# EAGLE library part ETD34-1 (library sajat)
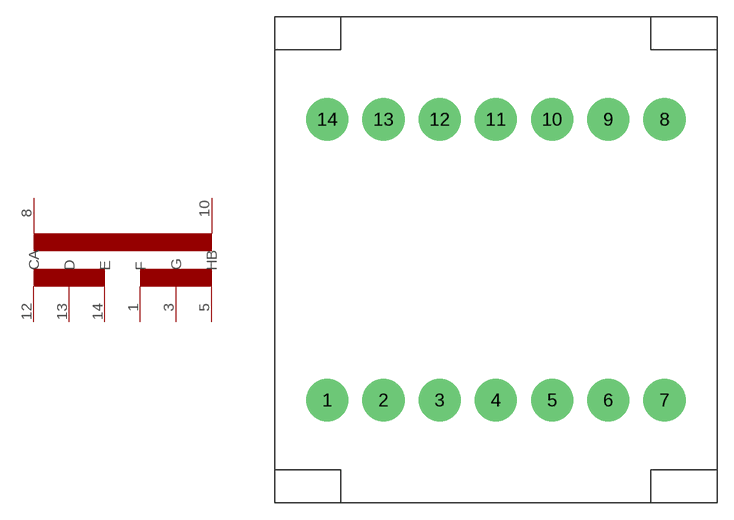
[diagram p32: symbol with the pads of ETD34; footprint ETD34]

Designator prefix -

## ETD34-1  [ETD34]
1  F
3  G
5  H
8  A
10  B
12  C
13  D
14  E

## Footprint ETD34 (pad centres in mm)
drill 0.6 pad 3.81 round: 1 -15.24,-12.7; 2 -10.16,-12.7; 3 -5.08,-12.7; 4 0,-12.7; 5 5.08,-12.7; 6 10.16,-12.7; 7 15.24,-12.7; 8 15.24,12.7; 9 10.16,12.7; 10 5.08,12.7; 11 0,12.7; 12 -5.08,12.7; 13 -10.16,12.7; 14 -15.24,12.7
